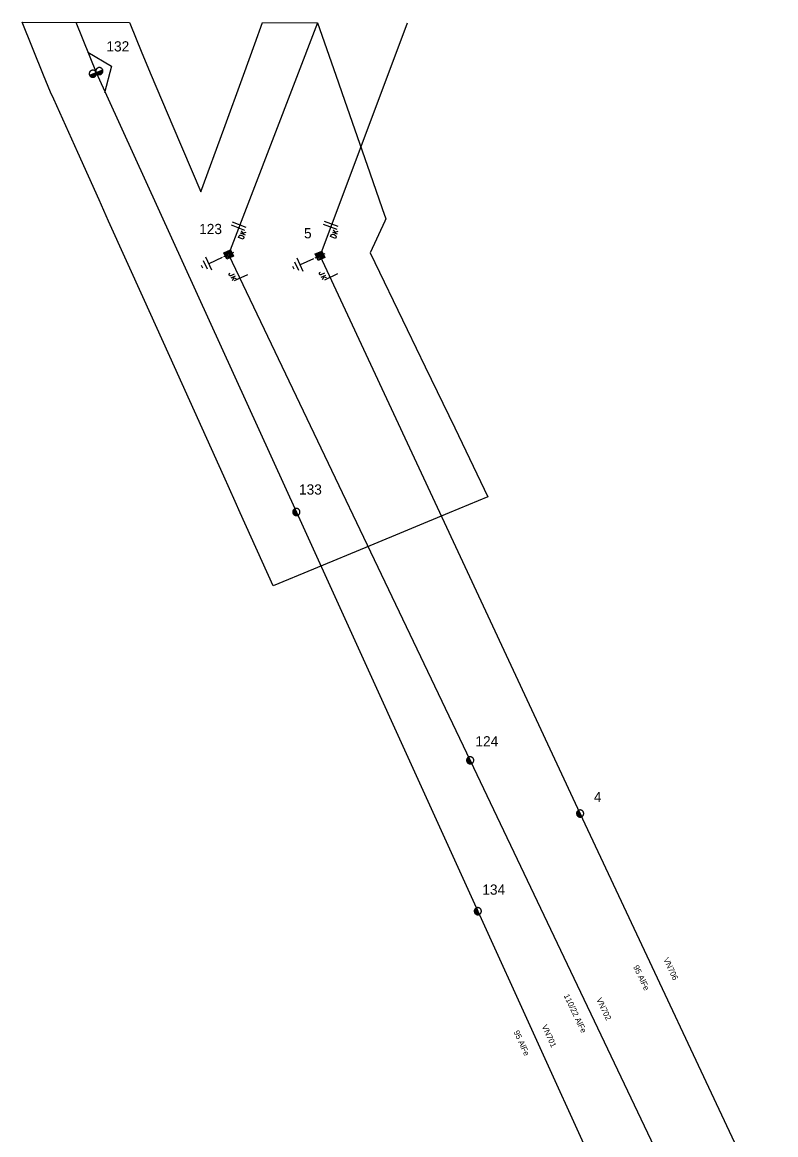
# Model space of a CAD drawing. Extents: x -536397 to -535454, y -1201642 to -1200953.
# Drawn here: x -536397 to -536267.9, y -1201144 to -1200953.5 of the extents above; entities that cross this region are included whole.
import ezdxf

# ---------------------------------------------------------------- set-up
doc = ezdxf.new("R2010")
doc.units = 0
for name, color, linetype in [('DOPLŇ_POPISY', 7, 'Continuous'), ('ELE_EON', 7, 'Continuous'), ('ELE_EON_POPIS', 7, 'Continuous'), ('KN_HRAN_POHYBLIVÁ', 7, 'Continuous'), ('PK_HRAN_SPORNÁ', 7, 'Continuous'), ('PLG_EXPORT_GPE', 7, 'Continuous'), ('RÁMEČEK', 7, 'Continuous'), ('SDEL_EON', 7, 'Continuous')]:
    doc.layers.add(name, color=color, linetype=linetype)

# ---------------------------------------------------------------- blocks, each defined once
blk = doc.blocks.new('VN850')
at = {"layer": 'RÁMEČEK'}
for points in [[(-0.56, 1.43), (-0.56, -1.07)], [(-0.01, 1.43), (-0.01, -1.07)], [(-2.09, -0.54), (-1.78, -0.54)], [(-2.09, -1.41), (-2.09, -0.54)], [(-1.78, -1.41), (-2.09, -1.41)], [(-1.78, -0.54), (-1.66, -0.6)], [(-1.67, -1.35), (-1.78, -1.41)], [(-1.59, -1.2), (-1.67, -1.35)], [(-1.66, -0.6), (-1.59, -0.75)], [(-1.59, -0.75), (-1.55, -0.96)], [(-1.55, -0.96), (-1.59, -1.2)], [(-1.26, -0.54), (-1.26, -1.41)], [(-0.85, -0.54), (-1.26, -1.09)], [(-1.13, -0.92), (-0.77, -1.41)]]:
    blk.add_lwpolyline(points, dxfattribs=at)
blk = doc.blocks.new('VN840')
at = {"layer": 'RÁMEČEK'}
for points in [[(-0.01, 1.41), (-0.01, -1.09)], [(-1.51, -1.24), (-1.51, -1.15)], [(-1.48, -1.35), (-1.51, -1.24)], [(-1.33, -1.42), (-1.48, -1.35)], [(-1.27, -1.42), (-1.33, -1.42)], [(-1.13, -1.35), (-1.27, -1.42)], [(-1.09, -1.24), (-1.13, -1.35)], [(-1.09, -0.59), (-1.09, -1.24)], [(-0.68, -0.59), (-0.68, -1.42)], [(-0.68, -1.11), (-0.27, -0.59)], [(-0.54, -0.94), (-0.2, -1.42)]]:
    blk.add_lwpolyline(points, dxfattribs=at)
blk = doc.blocks.new('VN860')
at = {"layer": 'RÁMEČEK'}
for points in [[(-3.74, 0), (0.01, 2.82)], [(0.01, 2.82), (3.76, 0)]]:
    blk.add_lwpolyline(points, dxfattribs=at)
blk = doc.blocks.new('VN440')
at = {"layer": 'ELE_EON_POPIS'}
for points in [[(1.22, 0), (1.21, 0.13), (1.19, 0.25), (1.16, 0.38), (1.11, 0.5), (1.05, 0.61), (0.98, 0.72), (0.9, 0.82), (0.81, 0.91), (0.71, 0.99), (0.6, 1.06), (0.49, 1.12), (0.37, 1.16), (0.25, 1.2), (0.12, 1.22), (-0.01, 1.22), (-0.14, 1.22), (-0.26, 1.2), (-0.39, 1.16), (-0.51, 1.12), (-0.62, 1.06), (-0.73, 0.99), (-0.83, 0.91), (-0.92, 0.82), (-1, 0.72), (-1.07, 0.61), (-1.13, 0.5), (-1.18, 0.38), (-1.21, 0.25), (-1.23, 0.13), (-1.24, 0), (-1.23, -0.13), (-1.21, -0.26), (-1.18, -0.38), (-1.13, -0.5), (-1.07, -0.62), (-1, -0.73), (-0.92, -0.83), (-0.83, -0.92), (-0.73, -1), (-0.62, -1.07), (-0.51, -1.13), (-0.39, -1.17), (-0.26, -1.2), (-0.14, -1.23), (-0.01, -1.23), (0.12, -1.23), (0.25, -1.2), (0.37, -1.17), (0.49, -1.13), (0.6, -1.07), (0.71, -1), (0.81, -0.92), (0.9, -0.83), (0.98, -0.73), (1.05, -0.62), (1.11, -0.5), (1.16, -0.38), (1.19, -0.26), (1.21, -0.13), (1.22, 0)], [(-1.24, 0), (1.22, 0)], [(-1.18, -0.34), (1.1, -0.34)], [(-1.01, -0.63), (0.97, -0.63)], [(-0.74, -0.92), (0.68, -0.92)]]:
    blk.add_lwpolyline(points, dxfattribs=at)
blk = doc.blocks.new('VN810')
at = {"layer": 'PLG_EXPORT_GPE'}
for points in [[(0, -1.25), (0, -3.75)], [(1.25, -3.75), (-1.25, -3.75)], [(0.77, -4.37), (-0.8, -4.37)], [(0, -5), (-0.25, -5)], [(0.27, -5), (0, -5)]]:
    blk.add_lwpolyline(points, dxfattribs=at)
blk = doc.blocks.new('VN450')
at = {"layer": 'ELE_EON_POPIS'}
for points in [[(0, 0), (-0.01, 0.13), (-0.03, 0.25), (-0.06, 0.38), (-0.11, 0.5), (-0.16, 0.61), (-0.23, 0.72), (-0.31, 0.82), (-0.4, 0.91), (-0.5, 0.99), (-0.61, 1.06), (-0.72, 1.11), (-0.84, 1.16), (-0.97, 1.19), (-1.09, 1.21), (-1.22, 1.22), (-1.35, 1.21), (-1.47, 1.19), (-1.59, 1.16), (-1.71, 1.11), (-1.83, 1.06), (-1.93, 0.99), (-2.03, 0.91), (-2.12, 0.82), (-2.2, 0.72), (-2.27, 0.61), (-2.33, 0.5), (-2.38, 0.38), (-2.41, 0.25), (-2.43, 0.13), (-2.44, 0), (-2.43, -0.13), (-2.41, -0.25), (-2.38, -0.38), (-2.33, -0.5), (-2.27, -0.61), (-2.2, -0.72), (-2.12, -0.82), (-2.03, -0.91), (-1.93, -0.99), (-1.83, -1.06), (-1.71, -1.11), (-1.59, -1.16), (-1.47, -1.19), (-1.35, -1.21), (-1.22, -1.22), (-1.09, -1.21), (-0.97, -1.19), (-0.84, -1.16), (-0.72, -1.11), (-0.61, -1.06), (-0.5, -0.99), (-0.4, -0.91), (-0.31, -0.82), (-0.23, -0.72), (-0.16, -0.61), (-0.11, -0.5), (-0.06, -0.38), (-0.03, -0.25), (-0.01, -0.13), (0, 0)], [(-2.44, 0), (2.44, 0)], [(2.44, 0), (2.43, 0.13), (2.41, 0.25), (2.38, 0.38), (2.33, 0.5), (2.27, 0.61), (2.2, 0.72), (2.12, 0.82), (2.03, 0.91), (1.94, 0.99), (1.83, 1.06), (1.71, 1.11), (1.6, 1.16), (1.47, 1.19), (1.35, 1.21), (1.22, 1.22), (1.09, 1.21), (0.97, 1.19), (0.84, 1.16), (0.72, 1.11), (0.61, 1.06), (0.5, 0.99), (0.4, 0.91), (0.31, 0.82), (0.23, 0.72), (0.16, 0.61), (0.11, 0.5), (0.06, 0.38), (0.03, 0.25), (0.01, 0.13), (0, 0), (0.01, -0.13), (0.03, -0.25), (0.06, -0.38), (0.11, -0.5), (0.16, -0.61), (0.23, -0.72), (0.31, -0.82), (0.4, -0.91), (0.5, -0.99), (0.61, -1.06), (0.72, -1.11), (0.84, -1.16), (0.97, -1.19), (1.09, -1.21), (1.22, -1.22), (1.35, -1.21), (1.47, -1.19), (1.6, -1.16), (1.71, -1.11), (1.83, -1.06), (1.94, -0.99), (2.03, -0.91), (2.12, -0.82), (2.2, -0.72), (2.27, -0.61), (2.33, -0.5), (2.38, -0.38), (2.41, -0.25), (2.43, -0.13), (2.44, 0)], [(-2.4, -0.31), (-0.04, -0.31)], [(-2.26, -0.61), (-0.17, -0.61)], [(-2.01, -0.92), (-0.42, -0.92)], [(0.04, -0.31), (2.4, -0.31)], [(0.17, -0.61), (2.27, -0.61)], [(0.42, -0.92), (2.02, -0.92)]]:
    blk.add_lwpolyline(points, dxfattribs=at)
blk = doc.blocks.new('VN470')
at = {"layer": 'ELE_EON_POPIS'}
for points in [[(-1.23, 1.22), (1.23, 1.22)], [(-1.23, -1.23), (-1.23, 1.22)], [(-0.92, 0.9), (0.92, 0.9)], [(-0.92, -0.95), (-0.92, 0.9)], [(-0.61, 0.61), (0.61, 0.61)], [(-0.61, -0.62), (-0.61, 0.61)], [(-0.31, -0.27), (-0.31, 0.34)], [(-0.31, 0.34), (0.31, 0.34)], [(0, 1.22), (0, 1.97)], [(0.31, 0.34), (0.31, -0.27)], [(0.61, 0.61), (0.61, -0.62)], [(0.92, 0.9), (0.92, -0.95)], [(1.23, 1.22), (1.23, -1.23)], [(1.23, -1.23), (-1.23, -1.23)], [(0.92, -0.95), (-0.92, -0.95)], [(0.61, -0.62), (-0.61, -0.62)], [(0.31, -0.27), (-0.31, -0.27)], [(0, -1.23), (0, -1.98)]]:
    blk.add_lwpolyline(points, dxfattribs=at)

msp = doc.modelspace()

# ---------------------------------------------------------------- linework, layer by layer
at = {"layer": 'ELE_EON'}
for points in [[(-536387.85, -1200953.47), (-536384.37, -1200962.05), (-536350.06, -1201037.34), (-536318.97, -1201105.71), (-536289.66, -1201170.08)], [(-536346.44, -1200953.53), (-536361.66, -1200993.24), (-536320.28, -1201079.87), (-536279.58, -1201165.38)], [(-536267.93, -1201160.31), (-536301.44, -1201088.98), (-536346, -1200993.45), (-536331, -1200953.56)]]:
    msp.add_lwpolyline(points, dxfattribs=at)
at = {"layer": 'PK_HRAN_SPORNÁ'}
msp.add_lwpolyline([(-536397.02, -1200953.46), (-536378.67, -1200953.48), (-536378.62, -1200953.62), (-536376.56, -1200958.69), (-536374.94, -1200962.5), (-536371.23, -1200971.23), (-536366.43, -1200982.52), (-536362.5, -1200971.76), (-536359.12, -1200962.5), (-536357.17, -1200957.17), (-536355.84, -1200953.52), (-536346.45, -1200953.53), (-536343.32, -1200962.5), (-536341.82, -1200966.82), (-536337.5, -1200979.22), (-536335.36, -1200985.36), (-536334.75, -1200987.12), (-536334.92, -1200987.5), (-536337.41, -1200992.96), (-536331.08, -1201006.08), (-536327.97, -1201012.5), (-536322.94, -1201022.94), (-536317.23, -1201034.75), (-536323.88, -1201037.5), (-536337.5, -1201043.14), (-536347.11, -1201047.11), (-536354.04, -1201049.98), (-536359.67, -1201037.5), (-536360.55, -1201035.55), (-536362.5, -1201031.22), (-536368.32, -1201018.32), (-536370.94, -1201012.5), (-536376.09, -1201001.09), (-536382.22, -1200987.5), (-536383.86, -1200983.86), (-536387.5, -1200975.79), (-536391.63, -1200966.63), (-536392.18, -1200965.41), (-536393.36, -1200962.5)], close=True, dxfattribs=at)

# ---------------------------------------------------------------- block references
at = {"layer": 'DOPLŇ_POPISY'}
for name, p, xscale, yscale, rotation in [('VN450', (-536384.37, -1200962.05), 0.49999999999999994, 0.5000000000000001, 22.397824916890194), ('VN470', (-536361.66, -1200993.24), 0.5, 0.5, 115.29690551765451), ('VN470', (-536346, -1200993.45), 0.5, 0.5, -65.65063334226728), ('VN440', (-536350.06, -1201037.34), 0.5, 0.5, -65.50125562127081), ('VN440', (-536320.28, -1201079.87), 0.5, 0.5000000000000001, -64.46801662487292), ('VN440', (-536301.44, -1201088.98), 0.49999999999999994, 0.5000000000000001, -64.99310838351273), ('VN440', (-536318.97, -1201105.71), 0.5, 0.5, -65.54721389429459)]:
    msp.add_blockref(name, p, dxfattribs=dict(at, xscale=xscale, yscale=yscale, rotation=rotation))
at = {"layer": 'KN_HRAN_POHYBLIVÁ'}
for name, p, rotation in [('VN860', (-536384.37, -1200962.05), -67.60193612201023), ('VN850', (-536343.96, -1200988.02), 69.3990972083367), ('VN850', (-536359.72, -1200988.17), 69.02683880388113), ('VN840', (-536344.27, -1200997.17), -64.9932861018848), ('VN840', (-536359.72, -1200997.31), -64.46789164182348)]:
    msp.add_blockref(name, p, dxfattribs=dict(at, rotation=rotation))
at = {"layer": 'RÁMEČEK'}
for p, rotation in [((-536361.66, -1200993.24), -65.24771668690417), ((-536346, -1200993.45), -65.70422495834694)]:
    msp.add_blockref('VN810', p, dxfattribs=dict(at, rotation=rotation))

# ---------------------------------------------------------------- texts
at = {"layer": 'ELE_EON_POPIS'}
for s, rotation, p in [('95 AlFe', 295.164, (-536292.37, -1201115.23)), ('110/22 AlFe', 295.453, (-536304.28, -1201120.17)), ('95 AlFe', 294.481, (-536312.87, -1201126.39))]:
    msp.add_text(s, height=1, rotation=rotation, dxfattribs=at).set_placement(p)
at = {"layer": 'PLG_EXPORT_GPE'}
for s, p in [('132', (-536382.6, -1200958.46)), ('123', (-536366.71, -1200989.74)), ('5', (-536348.75, -1200990.46)), ('133', (-536349.6, -1201034.35)), ('124', (-536319.38, -1201077.48)), ('4', (-536299.09, -1201087.01)), ('134', (-536318.2, -1201102.88))]:
    msp.add_text(s, height=1.75, dxfattribs=at).set_placement(p)
at = {"layer": 'SDEL_EON'}
for s, rotation, p in [('VN706', 295.164, (-536287.22, -1201113.94)), ('VN702', 295.453, (-536298.7, -1201120.82)), ('VN701', 294.481, (-536308.04, -1201125.43))]:
    msp.add_text(s, height=1, rotation=rotation, dxfattribs=at).set_placement(p)

doc.saveas('drawing.dxf')
